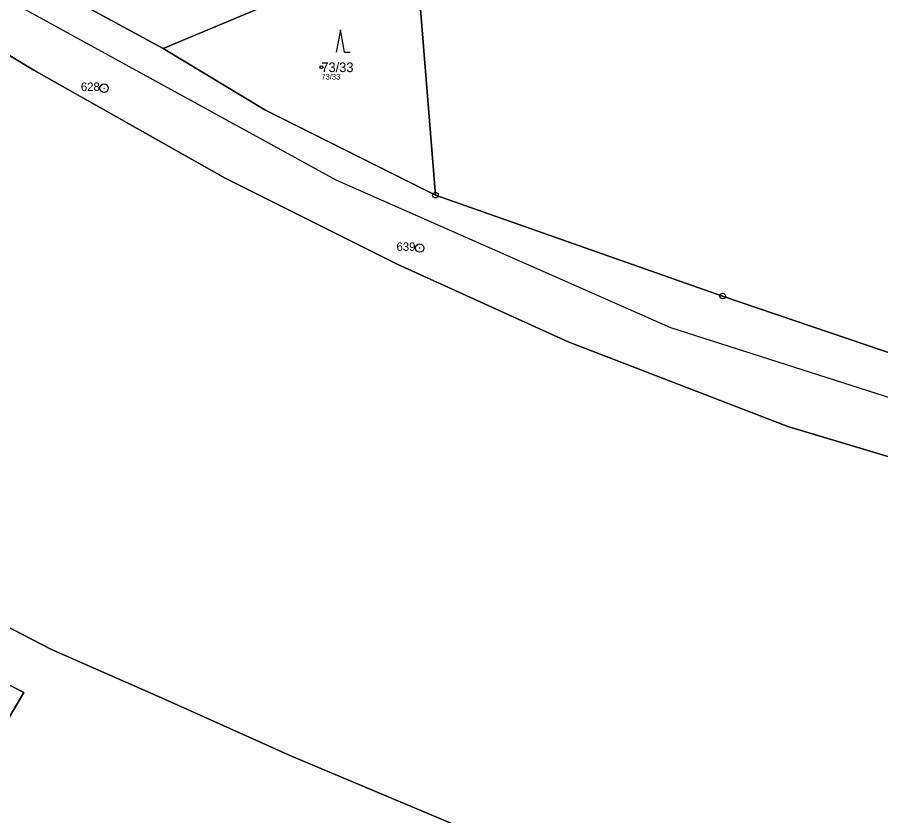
# Model space of a CAD drawing. Extents: x -734504 to -730695, y -1027923 to -1024502.
# Drawn here: x -732046 to -731893.3, y -1025962.2 to -1025821.1 of the extents above; entities that cross this region are included whole.
import ezdxf

# ---------------------------------------------------------------- set-up
doc = ezdxf.new("R2010")
doc.units = 0
for name, color, linetype in [('Definiční body', 7, 'Continuous'), ('Hranice parcel', 7, 'Continuous'), ('Parcelní čísla', 7, 'Continuous'), ('Polygon parcely', 7, 'Continuous'), ('Vnitřní kresba', 7, 'Continuous'), ('Značky bodu BP', 7, 'Continuous'), ('Značky kultur', 7, 'Continuous')]:
    doc.layers.add(name, color=color, linetype=linetype)

msp = doc.modelspace()

# ---------------------------------------------------------------- linework, layer by layer
at = {"layer": 'Definiční body'}
msp.add_circle((-731992.21, -1025829.9), 0.25, dxfattribs=at)
at = {"layer": 'Hranice parcel'}
for p, q in [((-731975.59, -1025807.89), (-732020.18, -1025826.56)), ((-731972.03, -1025852.49), (-731975.59, -1025807.89)), ((-732020.18, -1025826.56), (-732035.6, -1025818.19))]:
    msp.add_line(p, q, dxfattribs=at)
for points in [[(-732219.97, -1025723.8), (-732206.01, -1025731.56), (-732172.15, -1025751.49), (-732132.38, -1025775.79), (-732086.54, -1025804.21), (-732043.06, -1025830.43), (-732009.2, -1025849.51), (-731978.81, -1025864.67), (-731948.57, -1025878.39), (-731909.73, -1025893.38), (-731868.96, -1025905.55)], [(-732384.98, -1025753.2), (-732383.91, -1025753.95), (-732354.44, -1025774.74), (-732347.58, -1025773.7), (-732342.68, -1025779.81), (-732328.75, -1025781.15), (-732314.72, -1025787.4), (-732288.01, -1025800.65), (-732266.38, -1025811.08), (-732241.63, -1025823.94), (-732219.02, -1025835.61), (-732183.29, -1025855.27), (-732139.55, -1025879.56), (-732111.88, -1025894.19), (-732085.57, -1025909.23), (-732039.95, -1025932.78), (-732020.49, -1025941.32), (-731997.48, -1025951.64), (-731969.42, -1025963.44), (-731966.31, -1025967.48), (-731939.04, -1025983.53), (-731928.87, -1025976.86), (-731897.94, -1025983.64), (-731862.07, -1025991.44)], [(-731972.03, -1025852.49), (-732002.22, -1025837.4), (-732020.18, -1025826.56)], [(-731767.72, -1025909.1), (-731777.64, -1025908.38), (-731825.03, -1025897.69), (-731873.87, -1025886.45), (-731921.24, -1025870.32), (-731972.03, -1025852.49)], [(-732048.56, -1025946.68), (-732044.81, -1025940.38), (-732068.28, -1025928.31)]]:
    msp.add_lwpolyline(points, dxfattribs=at)
at = {"layer": 'Polygon parcely'}
for points in [[(-731886.8, -1025757.33), (-731921.87, -1025720.35), (-731945.31, -1025695.77), (-731947.44, -1025696.31), (-731952.62, -1025697.62), (-731969.43, -1025697.44), (-731974.6, -1025697.11), (-732009.17, -1025698.45), (-732007.19, -1025706.28), (-731999.51, -1025718.31), (-731994.44, -1025728.82), (-731987.37, -1025742.89), (-731984.96, -1025756.17), (-731983.17, -1025761.09), (-731982.62, -1025769.1), (-731980.98, -1025778.18), (-731977.2, -1025792.23), (-731975.72, -1025800.5), (-731975.59, -1025807.89), (-731972.03, -1025852.49), (-731921.24, -1025870.32), (-731873.87, -1025886.45)], [(-731836.02, -1025913.66), (-731868.96, -1025905.55), (-731909.73, -1025893.38), (-731948.57, -1025878.39), (-731978.81, -1025864.67), (-732009.2, -1025849.51), (-732043.06, -1025830.43), (-732086.54, -1025804.21), (-732132.38, -1025775.79), (-732172.15, -1025751.49), (-732206.01, -1025731.56), (-732219.97, -1025723.8), (-732240.2, -1025735.5), (-732319.4, -1025757.1), (-732384.98, -1025753.2)], [(-732384.98, -1025753.2), (-732383.91, -1025753.95), (-732354.44, -1025774.74), (-732347.58, -1025773.7), (-732342.68, -1025779.81), (-732328.75, -1025781.15), (-732314.72, -1025787.4), (-732288.01, -1025800.65), (-732266.38, -1025811.08), (-732241.63, -1025823.94), (-732219.02, -1025835.61), (-732183.29, -1025855.27), (-732139.55, -1025879.56), (-732111.88, -1025894.19), (-732085.57, -1025909.23), (-732039.95, -1025932.78), (-732020.49, -1025941.32), (-731997.48, -1025951.64), (-731969.42, -1025963.44), (-731966.31, -1025967.48), (-731939.04, -1025983.53), (-731928.87, -1025976.86), (-731897.94, -1025983.64), (-731862.07, -1025991.44)], [(-731928.87, -1025976.86), (-731939.04, -1025983.53), (-731966.31, -1025967.48), (-731969.42, -1025963.44), (-731997.48, -1025951.64), (-732020.49, -1025941.32), (-732039.95, -1025932.78), (-732085.57, -1025909.23), (-732111.88, -1025894.19), (-732139.55, -1025879.56), (-732183.29, -1025855.27), (-732219.02, -1025835.61), (-732241.63, -1025823.94), (-732266.38, -1025811.08), (-732288.01, -1025800.65), (-732314.72, -1025787.4), (-732328.75, -1025781.15), (-732342.68, -1025779.81), (-732347.58, -1025773.7), (-732354.44, -1025774.74)], [(-732086.54, -1025804.21), (-732043.06, -1025830.43), (-732009.2, -1025849.51), (-731978.81, -1025864.67), (-731948.57, -1025878.39), (-731909.73, -1025893.38), (-731868.96, -1025905.55)], [(-731873.87, -1025886.45), (-731921.24, -1025870.32), (-731972.03, -1025852.49), (-732002.22, -1025837.4), (-732020.18, -1025826.56), (-732035.6, -1025818.19)], [(-732068.28, -1025928.31), (-732044.81, -1025940.38), (-732048.56, -1025946.68)]]:
    msp.add_lwpolyline(points, dxfattribs=at)
for points in [[(-731975.59, -1025807.89), (-731978.35, -1025792.69), (-732035.91, -1025816.89), (-732035.6, -1025818.19), (-732020.18, -1025826.56)], [(-731975.59, -1025807.89), (-732020.18, -1025826.56), (-732002.22, -1025837.4), (-731972.03, -1025852.49)], [(-732044.81, -1025940.38), (-732068.28, -1025928.31), (-732071.41, -1025933.45), (-732066.62, -1025936.22), (-732051.5, -1025944.98), (-732048.56, -1025946.68)]]:
    msp.add_lwpolyline(points, close=True, dxfattribs=at)
at = {"layer": 'Vnitřní kresba'}
msp.add_lwpolyline([(-732211.71, -1025718.99), (-732161.33, -1025749.49), (-732061.61, -1025810.29), (-731989.67, -1025849.8), (-731930.48, -1025875.88), (-731863.58, -1025897.29), (-731797.93, -1025910.85), (-731733.26, -1025916.23), (-731645.7, -1025920.33), (-731574.56, -1025918.38), (-731403.14, -1025913.67), (-731373.71, -1025914.33)], dxfattribs=at)
at = {"layer": 'Značky bodu BP'}
for centre, radius in [((-732030.64, -1025833.59), 0.75), ((-732030.64, -1025833.59), 0.03), ((-731972.03, -1025852.49), 0.5), ((-731972.03, -1025852.49), 0.0303), ((-731974.82, -1025861.84), 0.75), ((-731974.82, -1025861.84), 0.03), ((-731921.24, -1025870.32), 0.5), ((-731921.24, -1025870.32), 0.0303)]:
    msp.add_circle(centre, radius, dxfattribs=at)
at = {"layer": 'Značky kultur'}
for p, q in [((-731988.84, -1025823.25), (-731989.59, -1025827.25)), ((-731988.09, -1025827.25), (-731988.84, -1025823.25)), ((-731988.09, -1025827.25), (-731987.09, -1025827.25))]:
    msp.add_line(p, q, dxfattribs=at)

# ---------------------------------------------------------------- texts
at = {"layer": 'Definiční body'}
msp.add_text('73/33', height=1, dxfattribs=at).set_placement((-731992.21, -1025832.06))
at = {"layer": 'Parcelní čísla'}
msp.add_text('73/33', height=1.7, dxfattribs=at).set_placement((-731992.21, -1025830.75))
at = {"layer": 'Značky bodu BP'}
for s, p in [('628', (-732034.74, -1025834.09)), ('639', (-731978.92, -1025862.34))]:
    msp.add_text(s, height=1.5, dxfattribs=at).set_placement(p)

doc.saveas('drawing.dxf')
